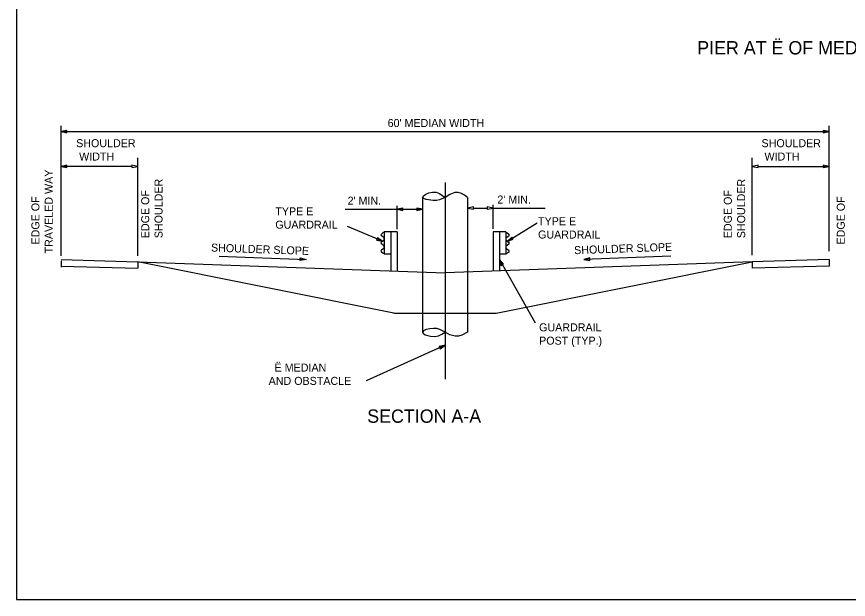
# Model space of a CAD drawing. Extents: x -439.1 to -407.9, y -458.1 to -436.2.
# Drawn here: x -439.11 to -423.51, y -458.05 to -447.12 of the extents above; entities that cross this region are included whole.
import ezdxf

# ---------------------------------------------------------------- set-up
doc = ezdxf.new("R2010")
doc.units = 0
doc.layers.add('Bridge-Named Boundary', color=7, linetype='Continuous')
doc.layers.add('Default', color=7, linetype='Continuous')

msp = doc.modelspace()

# ---------------------------------------------------------------- linework, layer by layer
at = {"layer": 'Bridge-Named Boundary'}
msp.add_lwpolyline([(-439.109, -458.051), (-407.859, -458.051), (-407.859, -437.676), (-439.109, -437.676)], close=True, dxfattribs=at)
at = {"layer": 'Default'}
for p, q in [((-438.276, -451.612), (-438.276, -449.17)), ((-423.876, -451.52), (-423.876, -449.17)), ((-438.276, -449.28), (-423.876, -449.28)), ((-436.836, -451.612), (-436.836, -449.772)), ((-425.316, -451.599), (-425.316, -449.772)), ((-423.876, -450.029), (-423.876, -449.874)), ((-436.947, -449.934), (-438.276, -449.934)), ((-425.206, -449.934), (-423.876, -449.934)), ((-431.077, -450.237), (-431.077, -453.919)), ((-431.497, -450.514), (-431.497, -451.916)), ((-430.657, -450.514), (-430.657, -451.916)), ((-431.976, -451.11), (-431.976, -450.67)), ((-430.176, -451.102), (-430.176, -450.652)), ((-432.948, -450.736), (-431.976, -450.736)), ((-431.976, -450.736), (-431.496, -450.736)), ((-430.546, -450.714), (-430.287, -450.714)), ((-430.176, -450.714), (-429.198, -450.714)), ((-432.248, -451.337), (-432.903, -451.062)), ((-429.904, -451.337), (-429.35, -450.993)), ((-432.271, -451.2), (-432.235, -451.174)), ((-432.224, -451.267), (-432.271, -451.234)), ((-432.216, -451.171), (-432.235, -451.174)), ((-431.976, -451.161), (-432.216, -451.161)), ((-432.216, -451.161), (-432.216, -451.578)), ((-432.216, -451.304), (-432.216, -451.282)), ((-432.216, -451.304), (-432.216, -451.282)), ((-432.096, -451.161), (-432.096, -451.894)), ((-431.976, -451.161), (-431.976, -451.899)), ((-429.936, -451.161), (-430.176, -451.161)), ((-430.176, -451.161), (-430.176, -451.899)), ((-430.056, -451.161), (-430.056, -451.894)), ((-429.936, -451.161), (-429.936, -451.578)), ((-429.936, -451.171), (-429.916, -451.174)), ((-429.936, -451.282), (-429.936, -451.304)), ((-429.936, -451.282), (-429.936, -451.304)), ((-429.928, -451.267), (-429.88, -451.234)), ((-429.916, -451.174), (-429.88, -451.2)), ((-432.224, -451.32), (-432.271, -451.353)), ((-432.224, -451.419), (-432.271, -451.386)), ((-432.216, -451.457), (-432.216, -451.434)), ((-429.936, -451.434), (-429.936, -451.457)), ((-429.928, -451.32), (-429.88, -451.353)), ((-429.928, -451.419), (-429.88, -451.386)), ((-432.224, -451.472), (-432.271, -451.505)), ((-432.235, -451.565), (-432.271, -451.538)), ((-432.216, -451.568), (-432.235, -451.565)), ((-432.096, -451.578), (-432.216, -451.578)), ((-429.936, -451.578), (-430.056, -451.578)), ((-429.936, -451.568), (-429.916, -451.565)), ((-429.928, -451.472), (-429.88, -451.505)), ((-429.88, -451.538), (-429.916, -451.565)), ((-438.277, -451.681), (-436.837, -451.722)), ((-438.277, -451.7), (-438.277, -451.82)), ((-436.837, -451.722), (-431.077, -451.931)), ((-432.037, -452.682), (-436.837, -451.722)), ((-436.836, -451.722), (-436.836, -451.842)), ((-435.313, -451.616), (-433.68, -451.675)), ((-425.317, -451.722), (-431.077, -451.931)), ((-430.117, -452.682), (-425.317, -451.722)), ((-430.056, -451.681), (-429.387, -452.867)), ((-426.841, -451.616), (-428.473, -451.675)), ((-423.877, -451.681), (-425.317, -451.722)), ((-425.317, -451.722), (-425.317, -451.842)), ((-423.877, -451.681), (-423.877, -451.801)), ((-438.277, -451.801), (-436.836, -451.842)), ((-431.497, -451.916), (-431.497, -453.04)), ((-430.657, -451.916), (-430.657, -453.04)), ((-423.877, -451.801), (-425.317, -451.842)), ((-432.037, -452.682), (-430.117, -452.682)), ((-431.077, -453.284), (-432.554, -453.952))]:
    msp.add_line(p, q, dxfattribs=at)
for points in [[(-438.166, -449.257), (-438.276, -449.28), (-438.166, -449.303)], [(-423.987, -449.303), (-423.876, -449.28), (-423.987, -449.257)], [(-438.166, -449.911), (-438.276, -449.934), (-438.166, -449.956)], [(-436.947, -449.956), (-436.836, -449.934), (-436.947, -449.911)], [(-425.206, -449.911), (-425.316, -449.934), (-425.206, -449.956)], [(-423.987, -449.956), (-423.876, -449.934), (-423.987, -449.911)], [(-431.866, -450.714), (-431.976, -450.736), (-431.866, -450.759)], [(-431.607, -450.759), (-431.496, -450.736), (-431.607, -450.714)], [(-430.546, -450.691), (-430.656, -450.714), (-430.546, -450.737)], [(-430.287, -450.737), (-430.176, -450.714), (-430.287, -450.691)], [(-432.359, -451.315), (-432.248, -451.337), (-432.341, -451.273)], [(-429.822, -451.259), (-429.904, -451.337), (-429.798, -451.298)], [(-433.79, -451.648), (-433.68, -451.675), (-433.792, -451.694)], [(-429.982, -451.766), (-430.056, -451.681), (-430.022, -451.788)], [(-428.364, -451.648), (-428.473, -451.675), (-428.362, -451.694)], [(-431.168, -453.351), (-431.077, -453.284), (-431.187, -453.309)]]:
    msp.add_lwpolyline(points, close=True, dxfattribs=at)
for points in [[(-430.656, -450.513), (-430.71, -450.474), (-430.77, -450.442), (-430.833, -450.423), (-430.896, -450.422), (-430.989, -450.459), (-431.076, -450.513), (-431.178, -450.558), (-431.236, -450.569), (-431.302, -450.571), (-431.429, -450.555), (-431.476, -450.537), (-431.496, -450.513), (-431.481, -450.484), (-431.438, -450.455), (-431.378, -450.43), (-431.314, -450.416), (-431.242, -450.418), (-431.181, -450.439), (-431.076, -450.513)], [(-430.657, -453.04), (-430.765, -453.099), (-430.825, -453.115), (-430.885, -453.118), (-430.984, -453.091), (-431.077, -453.042), (-431.176, -452.99), (-431.232, -452.974), (-431.296, -452.969), (-431.365, -452.976), (-431.431, -452.993), (-431.48, -453.016), (-431.497, -453.044), (-431.482, -453.066), (-431.447, -453.088), (-431.35, -453.118), (-431.27, -453.122), (-431.2, -453.108), (-431.136, -453.08), (-431.077, -453.042)]]:
    msp.add_lwpolyline(points, dxfattribs=at)
for centre, radius, start, end in [((-432.259, -451.217), 0.0204, 126.149, 235), ((-432.235, -451.282), 0.0188, 0, 55), ((-429.917, -451.282), 0.0188, 125, 180), ((-429.893, -451.217), 0.0204, 305, 53.851), ((-432.259, -451.37), 0.0204, 125, 233.851), ((-432.235, -451.305), 0.0188, 305, 360), ((-432.235, -451.435), 0.0188, 0, 55), ((-429.917, -451.305), 0.0188, 180, 235), ((-429.917, -451.435), 0.0188, 125, 180), ((-429.893, -451.37), 0.0204, 306.149, 55), ((-432.259, -451.522), 0.0204, 125, 233.851), ((-432.235, -451.457), 0.0188, 305, 360), ((-429.917, -451.457), 0.0188, 180, 235), ((-429.893, -451.522), 0.0204, 306.149, 55)]:
    msp.add_arc(centre, radius, start, end, dxfattribs=at)

# ---------------------------------------------------------------- texts
for s, height, p in [('PIER AT Ë OF MEDIAN', 0.25, (-426.348, -447.833)), ("60' MEDIAN WIDTH", 0.15, (-432.153, -449.194)), ('SHOULDER', 0.15, (-437.993, -449.572)), ('SHOULDER', 0.15, (-425.143, -449.572)), (' WIDTH', 0.15, (-437.993, -449.822)), (' WIDTH', 0.15, (-425.143, -449.822)), ("2' MIN.", 0.15, (-432.904, -450.65)), ("2' MIN.", 0.15, (-430.096, -450.628)), ('TYPE E', 0.15, (-434.259, -450.85)), ('GUARDRAIL', 0.15, (-434.259, -451.1)), ('TYPE E', 0.15, (-429.333, -451.035)), ('GUARDRAIL', 0.15, (-429.333, -451.285)), ('GUARDRAIL', 0.15, (-429.313, -453.025)), ('POST (TYP.)', 0.15, (-429.313, -453.275)), ('  Ë MEDIAN', 0.15, (-434.384, -453.779)), ('AND OBSTACLE', 0.15, (-434.384, -454.029)), ('SECTION A-A', 0.25, (-432.536, -454.74))]:
    msp.add_text(s, height=height, dxfattribs=at).set_placement(p)
for s, rotation, p in [('TRAVELED WAY', 90, (-438.432, -451.564)), ('SHOULDER', 90, (-436.373, -451.279)), ('SHOULDER', 90, (-425.45, -451.279)), ('   EDGE OF ', 90, (-438.682, -451.564)), ('EDGE OF ', 90, (-436.623, -451.279)), ('EDGE OF ', 90, (-425.7, -451.279)), ('   EDGE OF ', 90, (-423.582, -451.564)), ('SHOULDER SLOPE', 357.9819, (-435.467, -451.528)), ('SHOULDER SLOPE', 2.0181, (-428.654, -451.579))]:
    msp.add_text(s, height=0.15, rotation=rotation, dxfattribs=at).set_placement(p)

doc.saveas('drawing.dxf')
